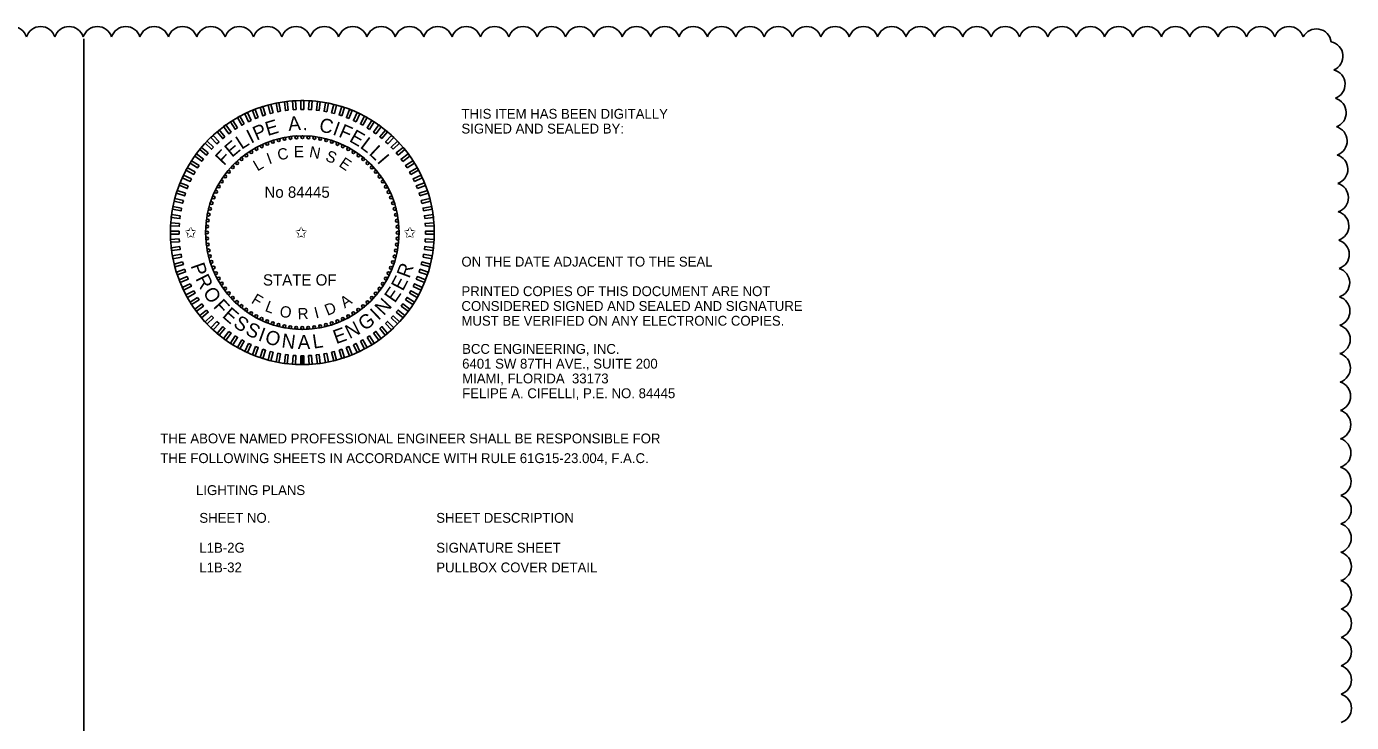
# Model space of a CAD drawing. Extents: x -811.2 to -767.6, y -2295.2 to -2235.1.
# Drawn here: x -777.02 to -767.6, y -2264.84 to -2259.9 of the extents above; entities that cross this region are included whole.
import ezdxf

# ---------------------------------------------------------------- set-up
doc = ezdxf.new("R2010")
doc.units = 0
for name, color, linetype in [('Cloud_dp', 7, 'Continuous'), ('PlotBorder_dp', 7, 'Continuous'), ('TextMinor', 7, 'Continuous'), ('TextMisc', 7, 'Continuous'), ('TextNotes', 7, 'Continuous'), ('TextShtNo', 7, 'Continuous')]:
    doc.layers.add(name, color=color, linetype=linetype)

msp = doc.modelspace()

# ---------------------------------------------------------------- linework, layer by layer
at = {"layer": 'Cloud_dp'}
for centre, radius, start, end in [((-777.1178, -2260.0023), 0.1057, 17.52079, 162.52079), ((-776.9163, -2260.0022), 0.1057, 17.51719, 162.51719), ((-776.7147, -2260.0022), 0.1057, 17.51375, 162.51375), ((-776.5132, -2260.0021), 0.1057, 17.51046, 162.51046), ((-776.3116, -2260.0021), 0.1057, 17.50731, 162.50731), ((-776.1101, -2260.0021), 0.1057, 17.50428, 162.50428), ((-775.9085, -2260.0021), 0.1057, 17.50138, 162.50138), ((-775.707, -2260.0021), 0.1057, 17.5, 162.5), ((-775.5054, -2260.0021), 0.1057, 17.5, 162.5), ((-775.3039, -2260.0021), 0.1057, 17.5, 162.5), ((-775.1023, -2260.0021), 0.1057, 17.5, 162.5), ((-774.9008, -2260.0021), 0.1057, 17.5, 162.5), ((-774.6992, -2260.0021), 0.1057, 17.5, 162.5), ((-774.4977, -2260.0021), 0.1057, 17.5, 162.5), ((-774.2961, -2260.0021), 0.1057, 17.5, 162.5), ((-774.0946, -2260.0021), 0.1057, 17.5, 162.5), ((-773.893, -2260.0021), 0.1057, 17.5, 162.5), ((-773.6915, -2260.0021), 0.1057, 17.5, 162.5), ((-773.4899, -2260.0021), 0.1057, 17.5, 162.5), ((-773.2884, -2260.0021), 0.1057, 17.5, 162.5), ((-773.0868, -2260.0021), 0.1057, 17.5, 162.5), ((-772.8853, -2260.0021), 0.1057, 17.5, 162.5), ((-772.6837, -2260.0021), 0.1057, 17.5, 162.5), ((-772.4822, -2260.0021), 0.1057, 17.5, 162.5), ((-772.2807, -2260.0021), 0.1057, 17.5, 162.5), ((-772.0791, -2260.0021), 0.1057, 17.5, 162.5), ((-771.8776, -2260.0021), 0.1057, 17.5, 162.5), ((-771.676, -2260.0021), 0.1057, 17.5, 162.5), ((-771.4745, -2260.0021), 0.1057, 17.5, 162.5), ((-771.2729, -2260.0021), 0.1057, 17.5, 162.5), ((-771.0714, -2260.0021), 0.1057, 17.5, 162.5), ((-770.8698, -2260.0021), 0.1057, 17.5, 162.5), ((-770.6683, -2260.0021), 0.1057, 17.5, 162.5), ((-770.4667, -2260.0021), 0.1057, 17.5, 162.5), ((-770.2652, -2260.0021), 0.1057, 17.5, 162.5), ((-770.0636, -2260.0021), 0.1057, 17.5, 162.5), ((-769.8621, -2260.0021), 0.1057, 17.5, 162.5), ((-769.6605, -2260.0021), 0.1057, 17.5, 162.5), ((-769.459, -2260.0021), 0.1057, 17.5, 162.5), ((-769.2574, -2260.0021), 0.1057, 17.5, 162.5), ((-769.0559, -2260.0021), 0.1057, 17.5, 162.5), ((-768.8543, -2260.0021), 0.1057, 17.5, 162.5), ((-768.6528, -2260.0021), 0.1057, 17.5, 162.5), ((-768.4512, -2260.0021), 0.1057, 17.5, 162.5), ((-768.2497, -2260.0021), 0.1057, 17.5, 162.5), ((-768.0481, -2260.0021), 0.1057, 17.5, 162.5), ((-767.8535, -2260.0187), 0.1056, 7.70605, 152.70605), ((-767.7706, -2260.108), 0.1057, 293.14506, 78.14506), ((-767.7558, -2260.3074), 0.1057, 290.35349, 75.35349), ((-767.7473, -2260.5083), 0.1057, 289.51862, 74.51862), ((-767.741, -2260.7095), 0.1057, 289.06556, 74.06556), ((-767.736, -2260.9109), 0.1057, 288.76987, 73.76987), ((-767.7319, -2261.1122), 0.1057, 288.55727, 73.55727), ((-767.7285, -2261.3137), 0.1057, 288.39488, 73.39488), ((-767.7255, -2261.5151), 0.1057, 288.2656, 73.2656), ((-767.723, -2261.7166), 0.1057, 288.1595, 73.1595), ((-767.7209, -2261.9181), 0.1057, 288.07039, 73.07039), ((-767.719, -2262.1196), 0.1057, 287.99417, 72.99417), ((-767.7174, -2262.3211), 0.1057, 287.928, 72.928), ((-767.716, -2262.5226), 0.1057, 287.86985, 72.86985), ((-767.7148, -2262.7241), 0.1057, 287.81821, 72.81821), ((-767.7137, -2262.9256), 0.1057, 287.77197, 72.77197), ((-767.7128, -2263.1272), 0.1057, 287.73023, 72.73023), ((-767.7121, -2263.3287), 0.1057, 287.69232, 72.69232), ((-767.7115, -2263.5302), 0.1057, 287.65767, 72.65767), ((-767.711, -2263.7318), 0.1057, 287.62586, 72.62586), ((-767.7106, -2263.9333), 0.1057, 287.5965, 72.5965), ((-767.7103, -2264.1348), 0.1057, 287.56931, 72.56931), ((-767.7101, -2264.3364), 0.1057, 287.54402, 72.54402), ((-767.71, -2264.5379), 0.1057, 287.52043, 72.52043), ((-767.71, -2264.7394), 0.1057, 287.50076, 72.50076)]:
    msp.add_arc(centre, radius, start, end, dxfattribs=at)
at = {"layer": 'TextMinor'}
for radius in [0.9375, 0.6875]:
    msp.add_circle((-775.0577, -2261.3603), radius, dxfattribs=at)
at = {"layer": 'TextNotes'}
msp.add_line((-776.6105, -2269.5845), (-776.6105, -2259.9845), dxfattribs=at)
at = {"layer": 'TextShtNo'}
for p, q in [((-775.0677, -2262.2978), (-775.0679, -2262.2353)), ((-775.0577, -2262.2978), (-775.0579, -2262.2353)), ((-775.0477, -2262.2978), (-775.0479, -2262.2353))]:
    msp.add_line(p, q, dxfattribs=at)
for points in [[(-775.3184, -2260.525), (-775.3376, -2260.5312), (-775.3569, -2260.4718), (-775.3377, -2260.4656)], [(-775.2654, -2260.5102), (-775.285, -2260.5152), (-775.3005, -2260.4548), (-775.281, -2260.4498)], [(-775.2117, -2260.4989), (-775.2315, -2260.5026), (-775.2432, -2260.4413), (-775.2234, -2260.4375)], [(-775.1573, -2260.4909), (-775.1773, -2260.4934), (-775.1851, -2260.4315), (-775.1651, -2260.4289)], [(-775.1025, -2260.4864), (-775.1226, -2260.4876), (-775.1265, -2260.4253), (-775.1064, -2260.424)], [(-775.0475, -2260.4853), (-775.0677, -2260.4853), (-775.0677, -2260.4228), (-775.0475, -2260.4228)], [(-774.9926, -2260.4876), (-775.0127, -2260.4864), (-775.0088, -2260.4241), (-774.9887, -2260.4253)], [(-774.9379, -2260.4934), (-774.9579, -2260.4909), (-774.9501, -2260.429), (-774.9301, -2260.4315)], [(-774.8837, -2260.5027), (-774.9036, -2260.4989), (-774.8919, -2260.4376), (-774.872, -2260.4413)], [(-774.8302, -2260.5153), (-774.8498, -2260.5103), (-774.8342, -2260.4498), (-774.8147, -2260.4548)], [(-774.7776, -2260.5312), (-774.7968, -2260.525), (-774.7775, -2260.4656), (-774.7583, -2260.4719)], [(-775.518, -2260.616), (-775.535, -2260.6268), (-775.5685, -2260.5741), (-775.5514, -2260.5633)], [(-775.4703, -2260.5886), (-775.488, -2260.5983), (-775.5181, -2260.5436), (-775.5004, -2260.5339)], [(-775.421, -2260.5642), (-775.4393, -2260.5728), (-775.4659, -2260.5163), (-775.4476, -2260.5077)], [(-775.3703, -2260.543), (-775.3891, -2260.5504), (-775.4121, -2260.4923), (-775.3933, -2260.4849)], [(-774.7261, -2260.5505), (-774.7449, -2260.543), (-774.7219, -2260.485), (-774.7031, -2260.4924)], [(-774.6759, -2260.5729), (-774.6942, -2260.5643), (-774.6676, -2260.5078), (-774.6493, -2260.5164)], [(-774.6272, -2260.5984), (-774.6449, -2260.5887), (-774.6148, -2260.534), (-774.5971, -2260.5437)], [(-774.5802, -2260.6269), (-774.5973, -2260.6161), (-774.5638, -2260.5634), (-774.5468, -2260.5742)], [(-775.6076, -2260.6796), (-775.6232, -2260.6925), (-775.663, -2260.6443), (-775.6474, -2260.6315)], [(-775.5638, -2260.6464), (-775.5801, -2260.6583), (-775.6168, -2260.6078), (-775.6005, -2260.5959)], [(-774.5351, -2260.6584), (-774.5515, -2260.6465), (-774.5148, -2260.596), (-774.4984, -2260.6079)], [(-774.4921, -2260.6926), (-774.5076, -2260.6797), (-774.4678, -2260.6316), (-774.4523, -2260.6445)], [(-775.7254, -2260.7947), (-775.7383, -2260.8102), (-775.7864, -2260.7704), (-775.7735, -2260.7549)], [(-775.6886, -2260.7539), (-775.7024, -2260.7686), (-775.7479, -2260.7258), (-775.7341, -2260.7111)], [(-775.6493, -2260.7155), (-775.664, -2260.7293), (-775.7067, -2260.6838), (-775.692, -2260.6699)], [(-774.4513, -2260.7294), (-774.466, -2260.7156), (-774.4232, -2260.6701), (-774.4085, -2260.6839)], [(-774.4128, -2260.7687), (-774.4267, -2260.754), (-774.3812, -2260.7113), (-774.3673, -2260.726)], [(-774.377, -2260.8104), (-774.3898, -2260.7948), (-774.3417, -2260.755), (-774.3289, -2260.7706)], [(-775.791, -2260.8828), (-775.8019, -2260.8999), (-775.8546, -2260.8664), (-775.8438, -2260.8494)], [(-775.7596, -2260.8377), (-775.7715, -2260.8541), (-775.822, -2260.8174), (-775.8101, -2260.801)], [(-774.3438, -2260.8542), (-774.3557, -2260.8379), (-774.3051, -2260.8012), (-774.2933, -2260.8175)], [(-774.3134, -2260.9), (-774.3242, -2260.883), (-774.2715, -2260.8495), (-774.2607, -2260.8666)], [(-775.8196, -2260.9298), (-775.8293, -2260.9475), (-775.884, -2260.9174), (-775.8743, -2260.8997)], [(-774.286, -2260.9477), (-774.2957, -2260.93), (-774.241, -2260.8999), (-774.2313, -2260.9176)], [(-775.8675, -2261.0287), (-775.875, -2261.0475), (-775.933, -2261.0245), (-775.9256, -2261.0057)], [(-775.8451, -2260.9785), (-775.8537, -2260.9968), (-775.9102, -2260.9702), (-775.9016, -2260.9519)], [(-774.2616, -2260.9969), (-774.2702, -2260.9787), (-774.2137, -2260.9521), (-774.2051, -2260.9704)], [(-774.2404, -2261.0477), (-774.2478, -2261.0289), (-774.1897, -2261.0059), (-774.1823, -2261.0247)], [(-775.9027, -2261.1328), (-775.9077, -2261.1524), (-775.9682, -2261.1368), (-775.9632, -2261.1173)], [(-775.8867, -2261.0802), (-775.893, -2261.0994), (-775.9524, -2261.0801), (-775.9461, -2261.0609)], [(-774.2223, -2261.0996), (-774.2286, -2261.0804), (-774.1692, -2261.0611), (-774.163, -2261.0803)], [(-774.2076, -2261.1526), (-774.2126, -2261.133), (-774.1522, -2261.1175), (-774.1471, -2261.137)], [(-775.9153, -2261.1863), (-775.9191, -2261.2062), (-775.9804, -2261.1945), (-775.9766, -2261.1746)], [(-774.1963, -2261.2063), (-774.2, -2261.1865), (-774.1387, -2261.1748), (-774.1349, -2261.1946)], [(-775.9304, -2261.2952), (-775.9316, -2261.3153), (-775.9939, -2261.3114), (-775.9927, -2261.2913)], [(-775.9245, -2261.2405), (-775.9271, -2261.2606), (-775.989, -2261.2527), (-775.9865, -2261.2327)], [(-774.1883, -2261.2607), (-774.1908, -2261.2407), (-774.1289, -2261.2329), (-774.1263, -2261.2529)], [(-774.1837, -2261.3155), (-774.185, -2261.2954), (-774.1227, -2261.2915), (-774.1214, -2261.3116)], [(-775.9327, -2261.3501), (-775.9327, -2261.3703), (-775.9952, -2261.3703), (-775.9952, -2261.3501)], [(-775.9316, -2261.4051), (-775.9304, -2261.4252), (-775.9927, -2261.4291), (-775.994, -2261.409)], [(-774.185, -2261.4254), (-774.1838, -2261.4053), (-774.1214, -2261.4092), (-774.1227, -2261.4293)], [(-774.1827, -2261.3705), (-774.1827, -2261.3503), (-774.1202, -2261.3503), (-774.1202, -2261.3705)], [(-775.9271, -2261.4599), (-775.9246, -2261.4799), (-775.9865, -2261.4877), (-775.989, -2261.4677)], [(-774.1908, -2261.4801), (-774.1883, -2261.4601), (-774.1264, -2261.4679), (-774.1289, -2261.4879)], [(-775.9191, -2261.5143), (-775.9153, -2261.5341), (-775.9767, -2261.5458), (-775.9805, -2261.526)], [(-775.9078, -2261.568), (-775.9027, -2261.5876), (-775.9632, -2261.6031), (-775.9682, -2261.5836)], [(-774.2127, -2261.5878), (-774.2077, -2261.5682), (-774.1472, -2261.5838), (-774.1522, -2261.6033)], [(-774.2001, -2261.5343), (-774.1963, -2261.5144), (-774.135, -2261.5261), (-774.1387, -2261.546)], [(-775.893, -2261.621), (-775.8868, -2261.6402), (-775.9462, -2261.6595), (-775.9524, -2261.6403)], [(-775.875, -2261.673), (-775.8676, -2261.6917), (-775.9256, -2261.7147), (-775.9331, -2261.6959)], [(-774.2479, -2261.6919), (-774.2404, -2261.6731), (-774.1824, -2261.6961), (-774.1898, -2261.7149)], [(-774.2286, -2261.6404), (-774.2224, -2261.6212), (-774.163, -2261.6405), (-774.1693, -2261.6597)], [(-775.8538, -2261.7237), (-775.8452, -2261.7419), (-775.9017, -2261.7685), (-775.9103, -2261.7502)], [(-775.8294, -2261.7729), (-775.8197, -2261.7906), (-775.8744, -2261.8207), (-775.8841, -2261.803)], [(-774.2958, -2261.7908), (-774.2861, -2261.7731), (-774.2314, -2261.8032), (-774.2411, -2261.8209)], [(-774.2703, -2261.7421), (-774.2617, -2261.7238), (-774.2052, -2261.7504), (-774.2138, -2261.7687)], [(-775.802, -2261.8206), (-775.7911, -2261.8376), (-775.8439, -2261.8711), (-775.8547, -2261.854)], [(-775.7716, -2261.8664), (-775.7597, -2261.8827), (-775.8102, -2261.9194), (-775.8221, -2261.9031)], [(-774.3558, -2261.8829), (-774.3439, -2261.8665), (-774.2934, -2261.9032), (-774.3052, -2261.9196)], [(-774.3243, -2261.8378), (-774.3135, -2261.8207), (-774.2608, -2261.8542), (-774.2716, -2261.8712)], [(-775.7384, -2261.9102), (-775.7255, -2261.9258), (-775.7737, -2261.9656), (-775.7865, -2261.95)], [(-775.7025, -2261.9519), (-775.6887, -2261.9666), (-775.7342, -2262.0093), (-775.7481, -2261.9946)], [(-774.4268, -2261.9667), (-774.413, -2261.952), (-774.3675, -2261.9948), (-774.3813, -2262.0095)], [(-774.39, -2261.9259), (-774.3771, -2261.9104), (-774.329, -2261.9502), (-774.3419, -2261.9657)], [(-775.6641, -2261.9912), (-775.6494, -2262.005), (-775.6921, -2262.0505), (-775.7069, -2262.0367)], [(-775.6233, -2262.028), (-775.6078, -2262.0409), (-775.6476, -2262.089), (-775.6631, -2262.0761)], [(-775.5803, -2262.0622), (-775.5639, -2262.0741), (-775.6006, -2262.1246), (-775.617, -2262.1127)], [(-774.5516, -2262.0742), (-774.5353, -2262.0623), (-774.4986, -2262.1129), (-774.5149, -2262.1247)], [(-774.5078, -2262.041), (-774.4922, -2262.0281), (-774.4524, -2262.0763), (-774.468, -2262.0891)], [(-774.4661, -2262.0051), (-774.4514, -2261.9913), (-774.4087, -2262.0368), (-774.4234, -2262.0507)], [(-775.5352, -2262.0937), (-775.5181, -2262.1045), (-775.5516, -2262.1572), (-775.5686, -2262.1464)], [(-775.4882, -2262.1222), (-775.4705, -2262.1319), (-775.5006, -2262.1866), (-775.5182, -2262.1769)], [(-775.4395, -2262.1477), (-775.4212, -2262.1563), (-775.4478, -2262.2128), (-775.4661, -2262.2042)], [(-774.6943, -2262.1564), (-774.6761, -2262.1478), (-774.6495, -2262.2043), (-774.6678, -2262.2129)], [(-774.6451, -2262.132), (-774.6274, -2262.1223), (-774.5973, -2262.177), (-774.615, -2262.1867)], [(-774.5974, -2262.1046), (-774.5804, -2262.0938), (-774.5469, -2262.1465), (-774.564, -2262.1573)], [(-775.3893, -2262.1701), (-775.3705, -2262.1776), (-775.3935, -2262.2356), (-775.4123, -2262.2282)], [(-775.3378, -2262.1894), (-775.3186, -2262.1956), (-775.3379, -2262.255), (-775.3571, -2262.2487)], [(-775.2852, -2262.2053), (-775.2656, -2262.2103), (-775.2811, -2262.2708), (-775.3007, -2262.2658)], [(-775.2317, -2262.2179), (-775.2118, -2262.2217), (-775.2235, -2262.283), (-775.2434, -2262.2793)], [(-775.1775, -2262.2272), (-775.1574, -2262.2297), (-775.1653, -2262.2916), (-775.1853, -2262.2891)], [(-775.1228, -2262.233), (-775.1027, -2262.2342), (-775.1066, -2262.2966), (-775.1267, -2262.2953)], [(-775.0679, -2262.2353), (-775.0477, -2262.2353), (-775.0477, -2262.2978), (-775.0679, -2262.2978)], [(-775.0129, -2262.2342), (-774.9928, -2262.233), (-774.9888, -2262.2953), (-775.009, -2262.2966)], [(-774.9581, -2262.2297), (-774.9381, -2262.2272), (-774.9303, -2262.2891), (-774.9503, -2262.2917)], [(-774.9037, -2262.2217), (-774.8839, -2262.218), (-774.8722, -2262.2793), (-774.892, -2262.2831)], [(-774.8499, -2262.2104), (-774.8304, -2262.2054), (-774.8149, -2262.2658), (-774.8344, -2262.2709)], [(-774.797, -2262.1957), (-774.7778, -2262.1894), (-774.7585, -2262.2488), (-774.7777, -2262.255)], [(-774.745, -2262.1776), (-774.7263, -2262.1702), (-774.7033, -2262.2283), (-774.7221, -2262.2357)]]:
    msp.add_lwpolyline(points, close=True, dxfattribs=at)
for centre in [(-775.3836, -2260.7664), (-775.3456, -2260.7471), (-775.3066, -2260.7302), (-775.2665, -2260.7158), (-775.2256, -2260.704), (-775.1841, -2260.6947), (-775.142, -2260.6881), (-775.0997, -2260.6841), (-775.0571, -2260.6828), (-775.0146, -2260.6842), (-774.9722, -2260.6882), (-774.9302, -2260.6949), (-774.8887, -2260.7043), (-774.8478, -2260.7162), (-774.8078, -2260.7306), (-774.7687, -2260.7476), (-775.4891, -2260.8379), (-775.4554, -2260.8119), (-775.4202, -2260.788), (-774.7308, -2260.7669), (-774.6942, -2260.7886), (-774.659, -2260.8125), (-774.6254, -2260.8387), (-775.5793, -2260.928), (-775.5512, -2260.8961), (-775.521, -2260.8661), (-774.5935, -2260.8668), (-774.5635, -2260.897), (-774.5353, -2260.9289), (-775.6511, -2261.0334), (-775.6294, -2260.9968), (-775.6054, -2260.9616), (-774.5093, -2260.9626), (-774.4854, -2260.9978), (-774.4638, -2261.0344), (-775.6874, -2261.1104), (-775.6704, -2261.0713), (-774.4445, -2261.0724), (-774.4276, -2261.1114), (-775.7231, -2261.2328), (-775.7137, -2261.1913), (-775.7018, -2261.1504), (-774.4132, -2261.1515), (-774.4014, -2261.1924), (-774.3921, -2261.2339), (-775.7338, -2261.3172), (-775.7297, -2261.2748), (-774.3855, -2261.276), (-774.3815, -2261.3183), (-775.7352, -2261.3597), (-775.7339, -2261.4023), (-774.3816, -2261.4034), (-774.3802, -2261.3609), (-775.7299, -2261.4447), (-775.7233, -2261.4867), (-774.3923, -2261.4878), (-774.3856, -2261.4458), (-775.714, -2261.5282), (-775.7022, -2261.5691), (-775.6878, -2261.6092), (-774.428, -2261.6102), (-774.4136, -2261.5702), (-774.4016, -2261.5293), (-775.6709, -2261.6482), (-775.6516, -2261.6862), (-774.4643, -2261.6872), (-774.4449, -2261.6493), (-775.63, -2261.7228), (-775.6061, -2261.7581), (-775.58, -2261.7917), (-774.5361, -2261.7926), (-774.5099, -2261.759), (-774.486, -2261.7238), (-775.5519, -2261.8236), (-775.5219, -2261.8538), (-775.49, -2261.8819), (-774.6263, -2261.8827), (-774.5943, -2261.8545), (-774.5642, -2261.8245), (-775.4564, -2261.9081), (-775.4212, -2261.932), (-775.3846, -2261.9537), (-775.3467, -2261.9731), (-775.3076, -2261.99), (-774.7698, -2261.9735), (-774.7318, -2261.9542), (-774.6952, -2261.9326), (-774.6599, -2261.9087), (-775.2676, -2262.0044), (-775.2267, -2262.0163), (-775.1852, -2262.0257), (-775.1432, -2262.0324), (-775.1008, -2262.0364), (-775.0577, -2262.0378), (-775.0157, -2262.0365), (-774.9733, -2262.0325), (-774.9313, -2262.0259), (-774.8898, -2262.0166), (-774.8489, -2262.0048), (-774.8088, -2261.9904)]:
    msp.add_circle(centre, 0.01, dxfattribs=at)

# ---------------------------------------------------------------- texts
at = {"layer": 'PlotBorder_dp'}
for s, p in [('THIS ITEM HAS BEEN DIGITALLY', (-773.9272, -2260.5516)), ('SIGNED AND SEALED BY:', (-773.9272, -2260.6566)), ('ON THE DATE ADJACENT TO THE SEAL', (-773.9272, -2261.6016)), ('PRINTED COPIES OF THIS DOCUMENT ARE NOT ', (-773.9272, -2261.8116)), ('CONSIDERED SIGNED AND SEALED AND SIGNATURE ', (-773.9272, -2261.9166)), ('MUST BE VERIFIED ON ANY ELECTRONIC COPIES.', (-773.9272, -2262.0216)), ('BCC ENGINEERING, INC.', (-773.9222, -2262.2215)), ('6401 SW 87TH AVE., SUITE 200', (-773.9222, -2262.3265)), ('MIAMI, FLORIDA  33173', (-773.9222, -2262.4315)), ('FELIPE A. CIFELLI, P.E. NO. 84445', (-773.9222, -2262.5365)), ('THE ABOVE NAMED PROFESSIONAL ENGINEER SHALL BE RESPONSIBLE FOR ', (-776.0663, -2262.8576)), ('THE FOLLOWING SHEETS IN ACCORDANCE WITH RULE 61G15-23.004, F.A.C.', (-776.0663, -2262.9976)), ('LIGHTING PLANS', (-775.8125, -2263.2246))]:
    msp.add_text(s, height=0.07, dxfattribs=at).set_placement(p)
at = {"layer": 'TextMisc'}
for s, p in [('SHEET NO.', (-775.7891, -2263.4216)), ('SHEET DESCRIPTION', (-774.1062, -2263.4216)), ('L1B-2G', (-775.7891, -2263.6338)), ('SIGNATURE SHEET', (-774.1062, -2263.6338)), ('L1B-32', (-775.7891, -2263.7738)), ('PULLBOX COVER DETAIL', (-774.1062, -2263.7738))]:
    msp.add_text(s, height=0.07, dxfattribs=at).set_placement(p)
at = {"layer": 'TextShtNo'}
for s, height, rotation, p in [('E', 0.1, 16.54261, (-775.3041, -2260.6746)), ('A', 0.1, 4.42103, (-775.1546, -2260.6381)), ('C', 0.1, 347.7999, (-774.944, -2260.6406)), ('I', 0.1, 26.81606, (-775.4224, -2260.7295)), ('P', 0.1, 23.28287, (-775.3829, -2260.7082)), ('.', 0.1, 356.65403, (-775.0561, -2260.6317)), ('I', 0.1, 340.0631, (-774.8481, -2260.6624)), ('F', 0.1, 336.52991, (-774.8055, -2260.6767)), ('E', 0.1, 330.07956, (-774.7303, -2260.7093)), ('E', 0.1, 40.12142, (-775.5578, -2260.8304)), ('L', 0.1, 33.07918, (-775.4891, -2260.7731)), ('E', 0.08, 0.41861, (-775.1174, -2260.8252)), ('N', 0.08, 349.29143, (-775.013, -2260.8238)), ('L', 0.1, 323.03732, (-774.653, -2260.7544)), ('L', 0.1, 316.7742, (-774.5893, -2260.8022)), ('F', 0.1, 46.57177, (-775.6142, -2260.8899)), ('L', 0.08, 30.40215, (-775.3768, -2260.9267)), ('I', 0.08, 20.01168, (-775.2934, -2260.8762)), ('C', 0.08, 12.20255, (-775.2254, -2260.8487)), ('S', 0.08, 337.02207, (-774.9, -2260.8455)), ('E', 0.08, 325.86633, (-774.8034, -2260.8857)), ('I', 0.1, 310.51108, (-774.5312, -2260.8566)), ('P', 0.1, 289.40551, (-775.8524, -2261.5949)), ('R', 0.1, 69.5134, (-774.2975, -2261.69)), ('R', 0.1, 296.14576, (-775.8194, -2261.6865)), ('E', 0.1, 62.47116, (-774.3437, -2261.7807)), ('O', 0.1, 303.96711, (-775.7679, -2261.7872)), ('E', 0.1, 55.42892, (-774.4006, -2261.8651)), ('F', 0.1, 312.62798, (-775.6955, -2261.8892)), ('F', 0.08, 328.72408, (-775.4257, -2261.8569)), ('L', 0.08, 339.29159, (-775.3284, -2261.916)), ('O', 0.08, 349.68206, (-775.2238, -2261.9557)), ('D', 0.08, 22.01279, (-774.8796, -2261.9522)), ('A', 0.08, 34.49917, (-774.7559, -2261.8997)), ('N', 0.1, 47.17876, (-774.4798, -2261.9542)), ('E', 0.1, 319.07833, (-775.6321, -2261.9575)), ('S', 0.1, 326.12056, (-775.5545, -2262.0234)), ('R', 0.08, 2.33977, (-775.0893, -2261.9776)), ('I', 0.08, 14.20366, (-774.9617, -2261.9709)), ('G', 0.1, 35.11153, (-774.6167, -2262.0618)), ('I', 0.1, 43.64556, (-774.5175, -2261.9886)), ('S', 0.1, 333.193, (-775.4691, -2262.0796)), ('I', 0.1, 340.26543, (-775.3774, -2262.1248)), ('O', 0.1, 343.79863, (-775.3297, -2262.143)), ('E', 0.1, 19.81912, (-774.8174, -2262.1533)), ('N', 0.1, 26.86136, (-774.722, -2262.1179)), ('N', 0.1, 352.45949, (-775.2087, -2262.175)), ('A', 0.1, 0.70966, (-775.0902, -2262.1883)), ('L', 0.1, 8.47665, (-774.978, -2262.1851))]:
    msp.add_text(s, height=height, rotation=rotation, dxfattribs=at).set_placement(p)
for s, p in [('No 84445', (-775.3267, -2261.1131)), ('✩', (-775.8927, -2261.3983)), ('✩', (-775.108, -2261.3983)), ('✩', (-774.3361, -2261.3983)), ('STATE OF', (-775.3374, -2261.7365))]:
    msp.add_text(s, height=0.08, dxfattribs=at).set_placement(p)

doc.saveas('drawing.dxf')
